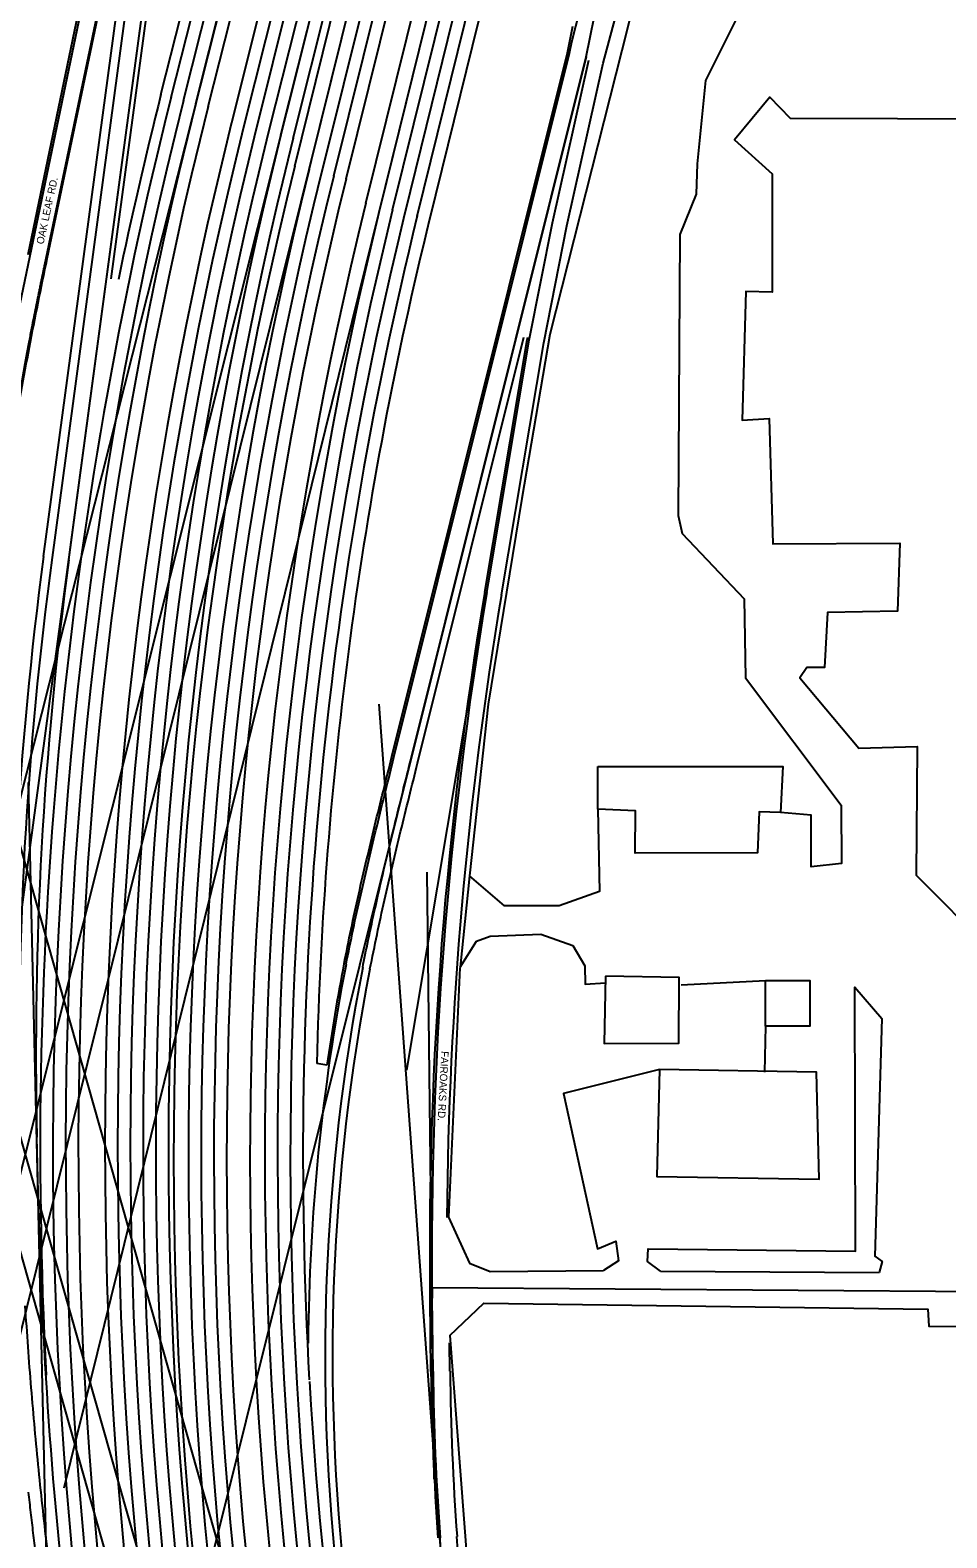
# Model space of a CAD drawing. Extents: x 227157 to 233208, y 434992 to 456232.
# Drawn here: x 228031 to 228896, y 442758 to 444181 of the extents above; entities that cross this region are included whole.
import ezdxf

# ---------------------------------------------------------------- set-up
doc = ezdxf.new("R2010")
doc.units = 0
for name, color, linetype in [('BD_X_Building', 7, 'Continuous'), ('Default', 7, 'Continuous'), ('GE_X_Alignment', 7, 'Continuous'), ('PM_X_Edge_Line', 7, 'Continuous'), ('PM_X_Lane_Line', 7, 'Continuous'), ('PV_X_EOP', 7, 'Continuous'), ('SV_X_Text_Name', 7, 'Continuous')]:
    doc.layers.add(name, color=color, linetype=linetype)

msp = doc.modelspace()

# ---------------------------------------------------------------- linework, layer by layer
at = {"layer": 'BD_X_Building'}
msp.add_lwpolyline([(228950.6, 444097), (228748.3, 444097.8), (228729, 444117.8), (228695.5, 444077.8), (228731.2, 444045.7), (228731.2, 443933.7), (228706.2, 443934.4), (228702.7, 443813.1), (228728.3, 443814.5), (228731.9, 443696.1), (228851.7, 443696.8), (228849.6, 443632.6), (228783.3, 443631.3), (228780.5, 443579.5), (228763.8, 443579.5), (228757.3, 443569.7), (228813, 443503.4), (228867.9, 443504.8), (228867.2, 443383.5), (229004.8, 443245.1)], dxfattribs=at)
for points in [[(228566.4, 443486), (228741.1, 443486), (228738.9, 443442.5), (228718.9, 443443.3), (228717.3, 443404.6), (228601.8, 443404.2), (228602.2, 443444.1), (228566.4, 443445.8)], [(228573.7, 443288.1), (228572.5, 443224.5), (228643, 443224.9), (228643.4, 443286.9)], [(228724.9, 443284), (228766.8, 443284), (228766.8, 443240.8), (228724.9, 443240.8)], [(228624.6, 443200), (228622.2, 443098.9), (228775.4, 443096.5), (228772.9, 443197.6)]]:
    msp.add_lwpolyline(points, close=True, dxfattribs=at)
at = {"layer": 'Default'}
for points, degree in [([(228040.8, 442268.2), (228037.7, 442284.1), (228026.5, 442339), (228009.1, 442439.7), (227997.1, 442519.8), (227985.8, 442605.8), (227976.6, 442690.4), (227969, 442775.7), (227963.1, 442860.9), (227959, 442946.3), (227956.6, 443031.8), (227956, 443117.2), (227957.1, 443202.7), (227960, 443288.1), (227964.6, 443373.5), (227970.9, 443458.7), (227979, 443543.9), (227988.8, 443628.5), (228000.5, 443714.4), (228013, 443794.4), (228030.9, 443895), (228042.4, 443949.9), (228045.6, 443965.8)], 2), ([(228041.7, 442268.4), (228036.2, 442296.2), (228025.2, 442352.1), (228010.8, 442436.2), (227998, 442520.8), (227986.9, 442605.5), (227977.6, 442690.5), (227970, 442775.7), (227964.1, 442860.9), (227960, 442946.3), (227957.6, 443031.8), (227957, 443117.2), (227958.1, 443202.7), (227961, 443288.1), (227965.6, 443373.5), (227971.9, 443458.7), (227980, 443543.8), (227989.8, 443628.7), (228001.4, 443713.3), (228014.6, 443797.8), (228029.5, 443881.9), (228040.9, 443937.7), (228046.6, 443965.6)], 3), ([(228326.9, 443299.6), (228329.1, 443310.6), (228333.5, 443332.6), (228340.7, 443365.4), (228348.2, 443398), (228356, 443430.6), (228364, 443463), (228369.4, 443484.6), (228372.1, 443495.4)], 3), ([(228328.8, 443299.3), (228331, 443310.2), (228335.4, 443332.2), (228342.6, 443364.9), (228350.2, 443397.6), (228358, 443430.1), (228366, 443462.5), (228371.4, 443484.1), (228374, 443494.9)], 3), ([(228351.4, 443294.9), (228353.6, 443305.7), (228357.9, 443327.4), (228365.1, 443359.9), (228372.6, 443392.3), (228380.3, 443424.7), (228388.3, 443457), (228393.7, 443478.6), (228396.4, 443489.3)], 3), ([(228025.6, 442976.9), (228026.5, 442964), (228028.2, 442938.1), (228031.2, 442899.4), (228034.6, 442860.7), (228038.3, 442822.1), (228042.3, 442783.5), (228046.7, 442744.9), (228051.4, 442706.4), (228056.5, 442667.9), (228061.9, 442629.5), (228067.6, 442591.1), (228073.7, 442552.8), (228080.2, 442514.6), (228086.9, 442476.4), (228094.1, 442438.3), (228101.5, 442400.3), (228109.3, 442362.3), (228117.4, 442324.4), (228125.9, 442286.6), (228134.7, 442248.9), (228140.8, 442223.8), (228143.9, 442211.3)], 3), ([(228088.8, 442419.2), (228087.5, 442425.5), (228085, 442438.2), (228081.3, 442457.1), (228077.7, 442476.1), (228074.1, 442495.1), (228070.7, 442514.1), (228067.3, 442533.1), (228064, 442552.1), (228060.8, 442571.2), (228057.7, 442590.2), (228054.7, 442609.3), (228051.7, 442628.4), (228048.9, 442647.5), (228046.1, 442666.7), (228043.4, 442685.8), (228040.8, 442705), (228038.3, 442724.1), (228035.8, 442743.3), (228033.5, 442762.5), (228031.2, 442781.7), (228029.8, 442794.5), (228029, 442800.9)], 3)]:
    msp.add_open_spline(points, degree=degree, dxfattribs=at)
at = {"layer": 'GE_X_Alignment'}
for p, q in [((228062.6, 442805), (229317.7, 447888.8)), ((227958.1, 442696), (228945.6, 446675.5)), ((227973.9, 442912.3), (228887.3, 446553.8)), ((227788.2, 442806.3), (228231.6, 444933.5)), ((228012.9, 443278.3), (228230.3, 444895.8)), ((227857.2, 442809.2), (228348.7, 444751.1)), ((228555.4, 444155.9), (228168.8, 442606.1)), ((228523.7, 443999.2), (228558, 444153)), ((228501.7, 443888.5), (228523.7, 443999.2)), ((228386.1, 443199.2), (228501.7, 443888.5)), ((229741.1, 437351.7), (227977.9, 443563.5)), ((228463.2, 442132.9), (228360.1, 443544.9)), ((228052, 442484.5), (228029.1, 443470.9)), ((229633.3, 437464.5), (227927.6, 443466.1)), ((228412.1, 442813.1), (228405.5, 443386.2)), ((229609.5, 437429.5), (227988.9, 443142.3)), ((228410, 442994.3), (229264.7, 442987.7))]:
    msp.add_line(p, q, dxfattribs=at)
for centre, radius, start, end in [((232085.6, 443125.1), 4021.6, 165.7953, 195.8413), ((232084, 443124.9), 3934.9, 165.9188, 195.8375), ((232051.4, 443117.2), 3871.4, 166.0643, 195.8658), ((231992.5, 443117.9), 3740.4, 166.1322, 195.846), ((231520.5, 443216.8), 3484.5, 172.3433, 181.3271), ((232177.2, 443027.2), 3767.4, 170.479, 180.6578), ((230232.5, 442928.3), 1923.5, 168.974, 186.6454), ((232377.5, 443171.8), 4340.2, 181.3271, 192.7831), ((230972.5, 442944.4), 2561.7, 180.6578, 184.177)]:
    msp.add_arc(centre, radius, start, end, dxfattribs=at)
msp.add_open_spline([(228344.5, 443296.2), (228346.1, 443304.4), (228349.4, 443320.7), (228356.4, 443353.3), (228365.7, 443393.9), (228375.5, 443434.4), (228383.5, 443466.8), (228387.6, 443483), (228389.6, 443491)], degree=3, dxfattribs=at)
at = {"layer": 'PM_X_Edge_Line'}
for p, q in [((228361.2, 444014.4), (228765.4, 445651.6)), ((228294, 444049.5), (228690.2, 445646.1)), ((228317.3, 444043.7), (228713.5, 445640.3)), ((228396.1, 444005.7), (228800.3, 445643)), ((228606.5, 445582.2), (228232.4, 444091)), ((228267.3, 444082.3), (228641.4, 445573.4)), ((228030.5, 443969), (228231.6, 444933.5)), ((228163.7, 444117.8), (228325.4, 444756.9)), ((228186.9, 444111.9), (228348.7, 444751.1)), ((228067, 443681.1), (228178.5, 444510.5)), ((228045.6, 443965.8), (228131.1, 444373.2)), ((228141.8, 444357.4), (228051.2, 443683.3)), ((228542, 444170.2), (228571.1, 444285.9)), ((228571.7, 444150), (228610.2, 444294)), ((228555.4, 444155.9), (228576.1, 444256.1)), ((228539.8, 444159.5), (228542, 444170.2)), ((228374, 443494.9), (228539.8, 444159.5)), ((228389.6, 443491), (228555.4, 444155.9)), ((228523.7, 443999.2), (228558, 444153)), ((228537.4, 443996.3), (228571.7, 444150)), ((228501.7, 443888.5), (228523.7, 443999.2)), ((228515.5, 443885.9), (228537.4, 443996.3)), ((228045.6, 443965.8), (228045.6, 443965.8)), ((228461.8, 443650.4), (228501.7, 443888.5)), ((228475.6, 443648), (228515.5, 443885.9)), ((228038.4, 443071.3), (228036.9, 443136.1)), ((228410.9, 442915), (228410.1, 442983.9)), ((228426.9, 442915.2), (228426.6, 442941.8)), ((228435.4, 442732.6), (228433.5, 442759)), ((228419.5, 442731.4), (228417.5, 442757.8))]:
    msp.add_line(p, q, dxfattribs=at)
for centre, radius, start, end in [((232085.6, 443125.1), 4045.6, 165.7953, 183.0268), ((232085.6, 443125.1), 4021.6, 165.7953, 195.8413), ((232084, 443124.9), 3970.9, 165.9188, 195.8375), ((232084, 443124.9), 3934.9, 165.9188, 195.8375), ((232051.4, 443117.2), 3871.4, 166.0643, 195.8658), ((232051.4, 443117.2), 3847.4, 166.0643, 195.8658), ((231992.5, 443117.9), 3740.4, 166.1322, 195.846), ((231992.5, 443117.9), 3704.4, 166.1322, 183.2642), ((231520.5, 443216.8), 3500.5, 172.3433, 181.3271), ((231520.5, 443216.8), 3484.5, 172.3433, 181.3271), ((232177.2, 443027.2), 3767.4, 170.479, 180.6578), ((232177.2, 443027.2), 3753.4, 170.479, 179.498), ((230232.5, 442928.3), 1939.5, 168.974, 179.6083), ((230232.5, 442928.3), 1923.5, 168.974, 186.6454), ((232377.5, 443171.8), 4340.2, 181.3271, 192.7831), ((230972.5, 442944.4), 2561.7, 180.6578, 184.177), ((230972.5, 442944.4), 2545.7, 180.6578, 184.177)]:
    msp.add_arc(centre, radius, start, end, dxfattribs=at)
msp.add_open_spline([(228344.5, 443296.2), (228346.1, 443304.4), (228349.4, 443320.7), (228356.4, 443353.3), (228365.7, 443393.9), (228375.5, 443434.4), (228383.5, 443466.8), (228387.6, 443483), (228389.6, 443491)], degree=3, dxfattribs=at)
at = {"layer": 'PM_X_Lane_Line'}
for p, q in [((228372.8, 444011.5), (228777, 445648.7)), ((228701.8, 445643.2), (228305.7, 444046.6)), ((228384.5, 444008.6), (228788.7, 445645.9)), ((228244.1, 444088.1), (228618.1, 445579.3)), ((228629.7, 445576.4), (228255.7, 444085.2)), ((228175.3, 444114.9), (228337.1, 444754))]:
    msp.add_line(p, q, dxfattribs=at)
for centre, radius, start, end in [((232085.6, 443125.1), 4033.6, 165.7953, 195.8413), ((232084, 443124.9), 3958.9, 165.9188, 195.8375), ((232084, 443124.9), 3946.9, 165.9188, 195.8375), ((232051.4, 443117.2), 3859.4, 166.0643, 195.8658), ((231992.5, 443117.9), 3728.4, 166.1322, 195.846), ((231992.5, 443117.9), 3716.4, 166.1322, 195.846), ((231992.5, 443117.9), 3704.4, 183.2897, 194.154)]:
    msp.add_arc(centre, radius, start, end, dxfattribs=at)
at = {"layer": 'PV_X_EOP'}
for p, q in [((228280.4, 444052.9), (228676.6, 445649.5)), ((228347.6, 444017.7), (228751.8, 445655)), ((228328.9, 444040.8), (228725.1, 445637.4)), ((228407.8, 444002.9), (228812, 445640.1)), ((228220.8, 444093.9), (228594.8, 445585.1)), ((228279, 444079.3), (228653, 445570.5)), ((228154, 444120.3), (228315.7, 444759.4)), ((228198.6, 444109), (228360.3, 444748.2)), ((228182.5, 444510), (228106.7, 443946.3)), ((228043.2, 443684.3), (228135.7, 444371.9)), ((228046.6, 443965.6), (228132.1, 444372.9)), ((228028.6, 443969.4), (228105.6, 444338.8)), ((228537.8, 444159.9), (228543, 444185)), ((228372.1, 443495.4), (228537.8, 444159.9)), ((228396.4, 443489.3), (228496.6, 443891.3)), ((228459.8, 443650.7), (228499.7, 443888.8)), ((228499.7, 443888.8), (228500.3, 443891.5)), ((228436.3, 443296.1), (228425.6, 443060.4)), ((228645.3, 443279.9), (228724.9, 443284)), ((228724.9, 443240.8), (228723.8, 443197.3)), ((228310.7, 443204.1), (228301.2, 443205.5)), ((228625.8, 443009.5), (228832.3, 443008.2)), ((228408.9, 442915), (228408.1, 442983.9))]:
    msp.add_line(p, q, dxfattribs=at)
for points in [[(228719.6, 444645.6), (228693, 444602.8), (228594.8, 444184.3), (228521.3, 443893.9), (228494.9, 443739.1), (228462.9, 443544.8), (228445.5, 443382.8)], [(228699.8, 444196.6), (228668.1, 444133.8), (228660.2, 444055), (228659.5, 444026.4), (228643.9, 443988.2), (228642.5, 443723), (228646.1, 443705.9), (228704.8, 443644.2), (228705.8, 443569.8), (228796.4, 443449.4), (228796.7, 443394.3), (228767.8, 443391.4), (228767.8, 443440.1), (228738.9, 443442.5)], [(228566.4, 443445.8), (228568.1, 443368.1), (228529.9, 443354.4), (228478.5, 443354.6), (228445.5, 443382.8), (228436.7, 443296.6), (228452, 443321), (228465, 443325.7), (228512.8, 443327.8), (228543, 443317), (228554.2, 443297.7), (228554.5, 443280.6), (228573.8, 443281.7)], [(228625.8, 443009.5), (228613.4, 443018.6), (228613.9, 443030.8), (228809.8, 443028.4), (228809.1, 443277.6), (228834.7, 443248), (228828.1, 443023.6), (228835.1, 443018.6), (228832.3, 443008.2)], [(228624.6, 443200), (228534, 443177.2), (228566.1, 443030.6), (228583.4, 443037.9), (228586.1, 443019.4), (228571.9, 443010.2)], [(228426.9, 442948.7), (228459, 442979.4), (228878.1, 442973.8), (228879, 442957.7), (229490.7, 442953.9), (229495.3, 442966.7), (229509.5, 442976.3), (229511.5, 443054.2), (229505.6, 443057.1), (229508.9, 443074), (229696.8, 443073.4)], [(228425.6, 443060.4), (228445.5, 443017.2), (228464.8, 443009.4), (228571.9, 443010.2)], [(228426.9, 442948.7), (228446.7, 442689.3), (228458.1, 442542.6), (228475.9, 442405.6)]]:
    msp.add_lwpolyline(points, dxfattribs=at)
for centre, radius, start, end in [((232085.6, 443125.1), 4055.6, 165.7953, 168.3247), ((232085.6, 443125.1), 4009.6, 165.7953, 195.8413), ((232084, 443124.9), 3982.9, 165.9188, 195.8375), ((232084, 443124.9), 3922.9, 165.9188, 195.8375), ((232051.4, 443117.2), 3885.4, 166.0643, 195.8658), ((232051.4, 443117.2), 3835.4, 166.0643, 195.8658), ((231992.5, 443117.9), 3754.4, 166.1322, 195.846), ((231992.5, 443117.9), 3692.4, 166.1322, 178.6404), ((231520.5, 443216.8), 3508.5, 172.3433, 181.3271), ((232177.2, 443027.2), 3769.4, 170.479, 180.6578), ((230232.5, 442928.3), 1941.5, 168.974, 171.835), ((230232.5, 442928.3), 1916.5, 168.974, 186.6454), ((230972.5, 442944.4), 2563.7, 180.6578, 184.177)]:
    msp.add_arc(centre, radius, start, end, dxfattribs=at)

# ---------------------------------------------------------------- texts
at = {"layer": 'SV_X_Text_Name'}
for s, rotation, p in [('OAK LEAF RD.', 77.7398, (228043.1, 443978.6)), ('FAIROAKS RD.', 267.0528, (228418.7, 443217.5))]:
    msp.add_text(s, height=7, rotation=rotation, dxfattribs=at).set_placement(p)

doc.saveas('drawing.dxf')
